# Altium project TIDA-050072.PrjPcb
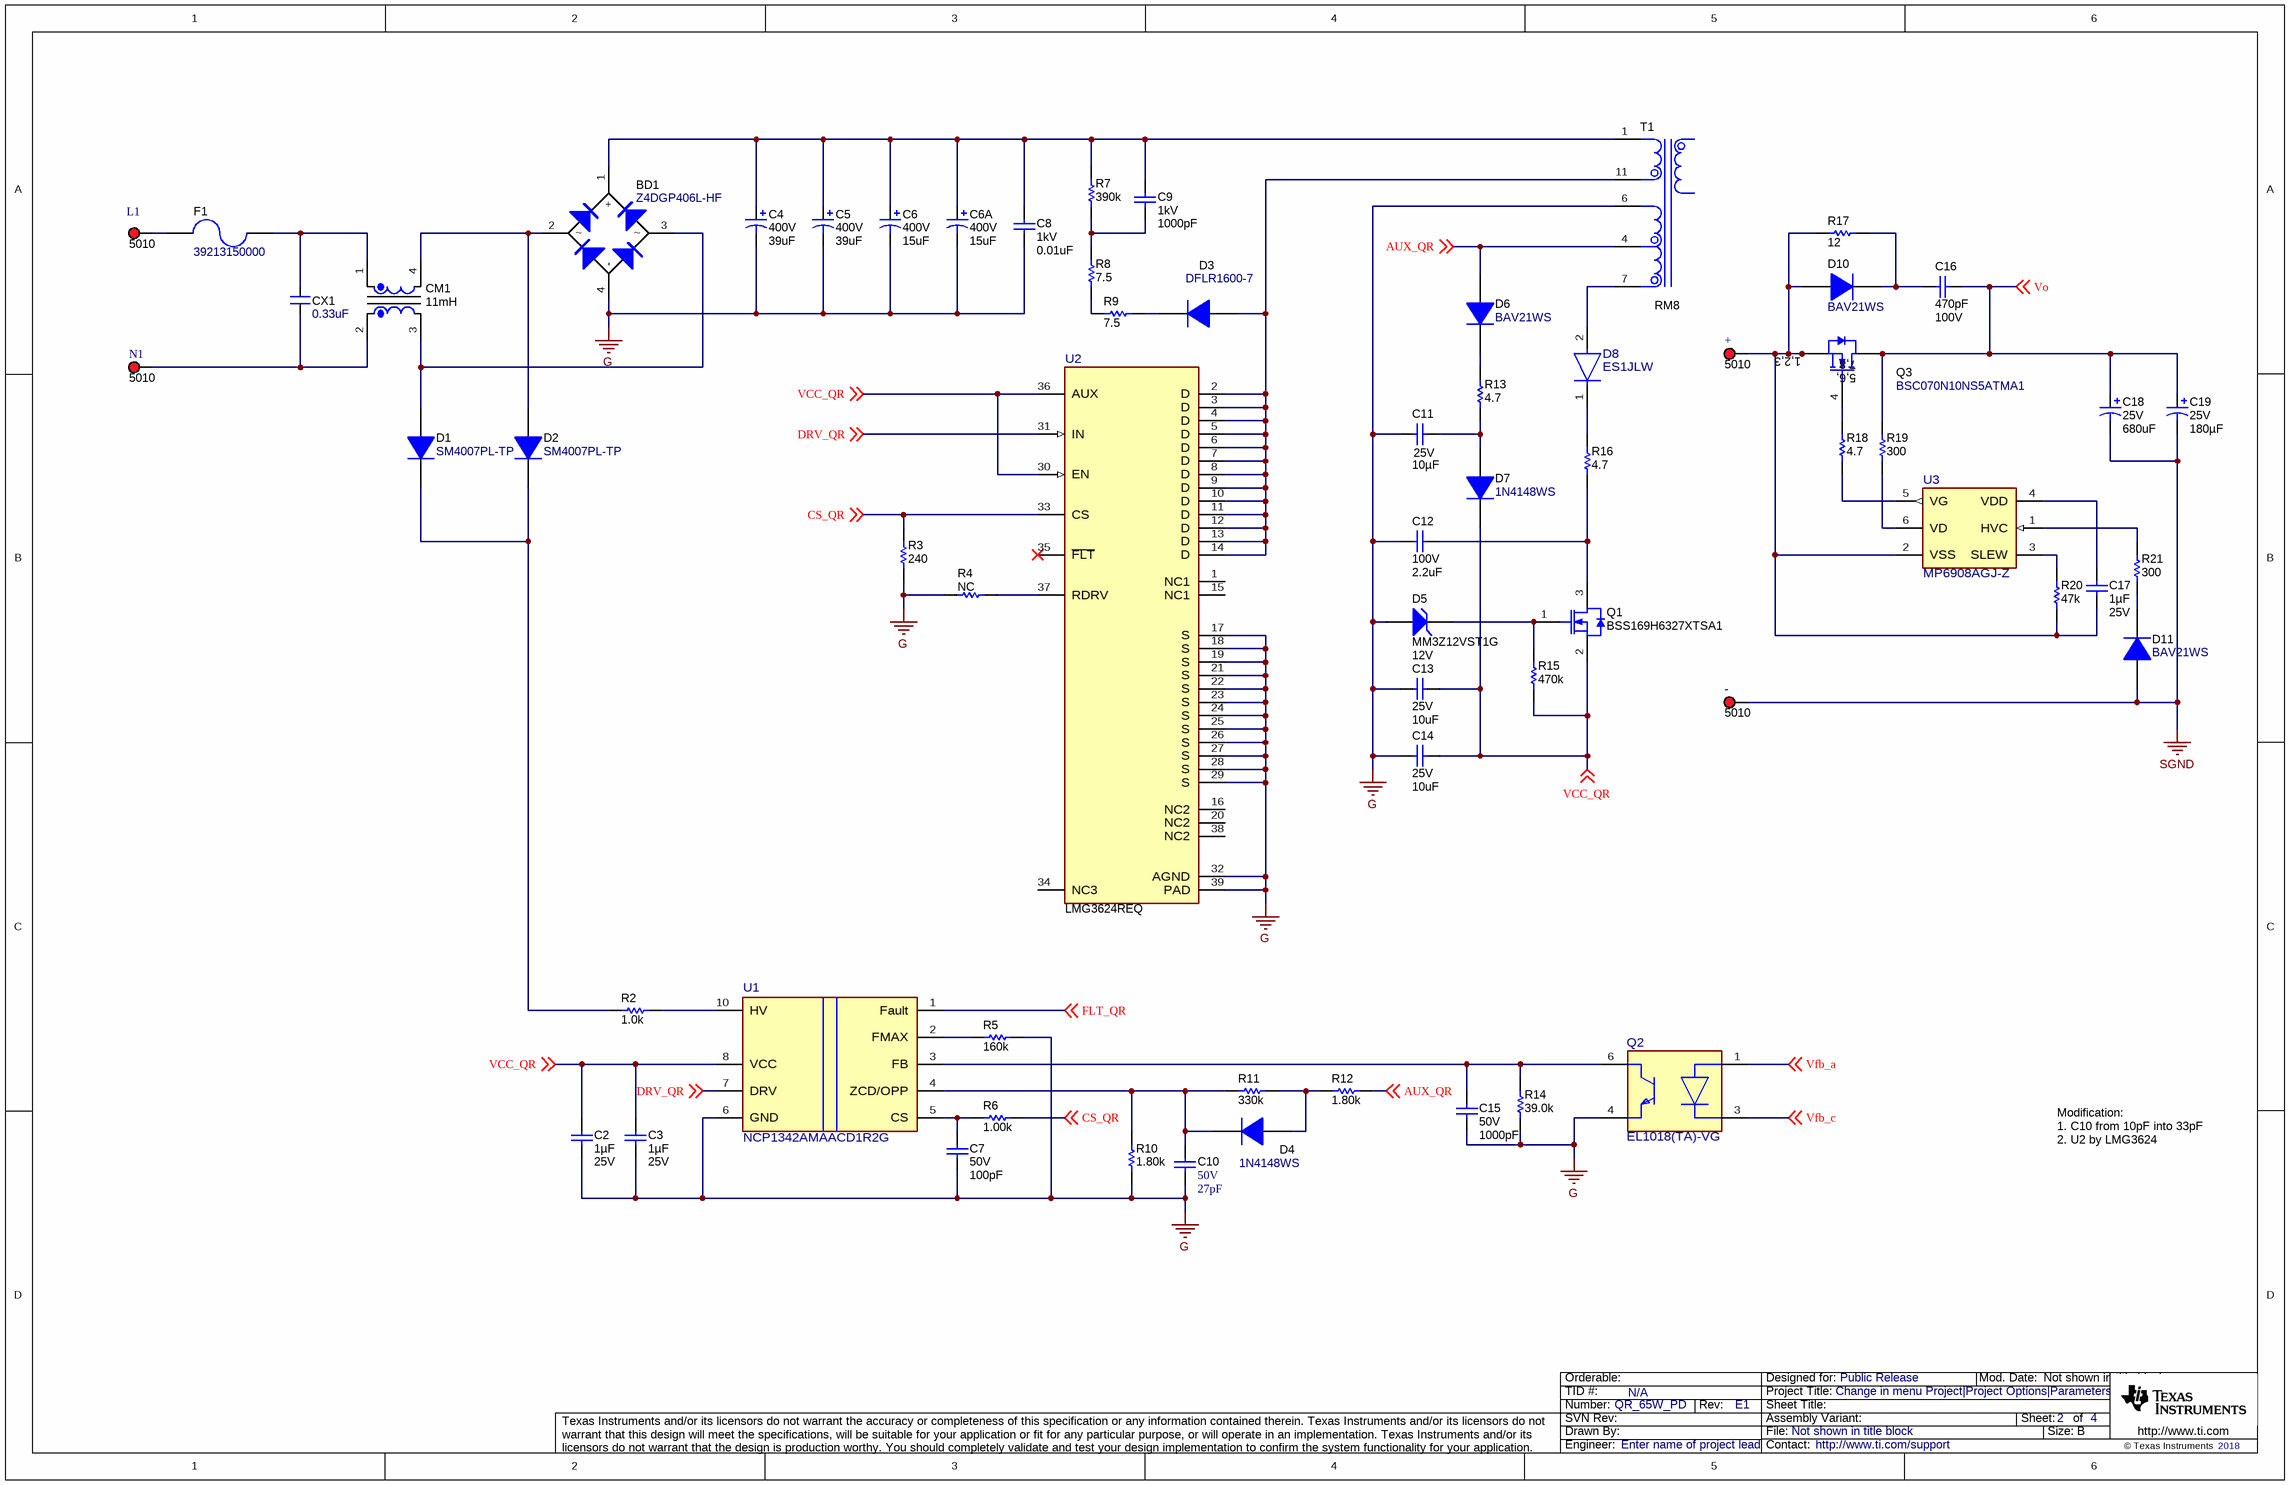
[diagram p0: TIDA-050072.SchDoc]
CopyrightYear: 2018; PCB_Layout: Who did the Layout?; PCB_Rev: E1; PRJ_Customer: Public Release; PRJ_Engineer: Enter name of project lead; PRJ_Number: QR_65W_PD; PRJ_Title: Change in menu Project|Project Options|Parameters; SCH_Rev: E1; TechSupport: http://www.ti.com/support; TID: N/A
5 sheets, 105 parts. Net scope: global (net labels, ports and power ports of the same name join across sheets).
Board file: TIDA-050072.PcbDoc
Sheets:
  TIDA-050072.SchDoc
  TIDA-050072_BlankSheet.SchDoc
  TIDA-050072_CoverSheet.SchDoc
  TIDA-050072_Hardware.SchDoc
  TIDA-050072_PD_Board.SchDoc

## Sheet TIDA-050072.SchDoc
size 431 x 279 mm; Date: Not shown in title block; ApprovedBy: Not shown in title block; CheckedBy: Not shown in title block; Author: Not shown in title block; CompanyName: Not shown in title block; Engineer: Not shown in title block; Organization: Not shown in title block; Address1: Not shown in title block; Address2: Not shown in title block; Address3: Not shown in title block; Address4: Not shown in title block; DocumentNumber: 2; Revision: Use project parameter SCH_Rev; SheetNumber: 2; SheetTotal: 4; PageSetup: Record=PageOptions¦CenterHorizontal=True¦CenterVertical=True¦PrintScale=1.00¦XCorrection=1.00¦YCorrection=1.00¦PrintKind=0¦BorderSize=5000000¦LeftOffset=0¦BottomOffset=0¦Orientation=2¦PaperLength=1000¦PaperWidth=1000¦Scale=100¦PaperSource=15¦PrintQuality=600¦MediaType=1¦DitherType=10¦PaperKind=Letter¦PrintScaleMode=1

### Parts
+  5010  [Keystone5010]
-  5010  [Keystone5010]
BD1  Z4DGP406L-HF  [Z4-D]
C2  Cap_F: 1µF  VDC_V: 25V  [0603_HV]  (hidden comment: GCM188R71E105KA64D)
C3  Cap_F: 1µF  VDC_V: 25V  [0603_HV]  (hidden comment: GCM188R71E105KA64D)
C4  VDC_V: 400V  ValueDisplayed: 39uF  [CY_1250x2000]  (hidden comment: 400LXW39MEFR12.5X20)
C5  VDC_V: 400V  ValueDisplayed: 39uF  [CY_1250x2000]  (hidden comment: 400LXW39MEFR12.5X20)
C6  VDC_V: 400V  ValueDisplayed: 15uF  [AX_800x900]  (hidden comment: 400AX4.7MTA8X9)
C6A  VDC_V: 400V  ValueDisplayed: 15uF  [AX_800x900]  (hidden comment: 400AX4.7MTA8X9)
C7  VDC_V: 50V  ValueDisplayed: 100pF  [0603_HV]  (hidden comment: C0603C101J5GAC)
C8  VDC_V: 1kV  ValueDisplayed: 0.01uF  [1206]  (hidden comment: VJ1206Y103KXGAT5Z)
C9  VDC_V: 1kV  ValueDisplayed: 1000pF  [1206]  (hidden comment: GRM31BR73A102KW01L)
C10  VDC_V: 50V  ValueDisplayed: 27pF  [0603]  (hidden comment: GRM1885C1H270JA01D)
C11  VDC_V: 25V  ValueDisplayed: 10µF  [0805]  (hidden comment: CC0805KKX5R8BB106)
C12  VDC_V: 100V  ValueDisplayed: 2.2uF  [1206_190]  (hidden comment: GRM31CR72A225KA73L)
C13  VDC_V: 25V  ValueDisplayed: 10uF  [1206_190]  (hidden comment: C3216X7R1E106K160AE)
C14  VDC_V: 25V  ValueDisplayed: 10uF  [1206_190]  (hidden comment: C3216X7R1E106K160AE)
C15  VDC_V: 50V  ValueDisplayed: 1000pF  [0603_HV]  (hidden comment: C0603C102J5GACTU)
C16  Cap_F: 470pF  VDC_V: 100V  [0603_HV]  (hidden comment: 06031C471KAT2A)
C17  Cap_F: 1µF  VDC_V: 25V  [0603_HV]  (hidden comment: GCM188R71E105KA64D)
C18  VDC_V: 25V  ValueDisplayed: 680uF  [Chemi-Con_800x1500]  (hidden comment: A750KW687M1EAAE016)
C19  VDC_V: 25V  ValueDisplayed: 180µF  [Panasonic_D8]  (hidden comment: EEH-ZKE181XUP)
CM1  11mH  [CM_20x11_planwire]
CX1  value 0.33uF  [Xcap_15x8.5]  (hidden comment: 890324024003)
D1  SM4007PL-TP  [SOD-123FL]
D2  SM4007PL-TP  [SOD-123FL]
D3  DFLR1600-7  [PowerDI123]
D4  1N4148WS  [SOD-323]
D5  MM3Z12VST1G  value 12V  [SOD-323]
D6  BAV21WS  [SOD-323]
D7  1N4148WS  [SOD-323]
D8  ES1JLW  [FP-UF1JLWHRVG_SOD-123-MFG]
D10  BAV21WS  [SOD-323]
D11  BAV21WS  [SOD-323]
F1  39213150000  [FUSE_392]
L1  5010  [Keystone5010]
N1  5010  [Keystone5010]
Q1  BSS169H6327XTSA1  [SOT-23]
Q2  EL1018(TA)-VG  [FP-TLP383(GR-TPL,E_SO6-4-MFG]
Q3  BSC070N10NS5ATMA1  [PG-TDSON-8]
R2  ValueDisplayed: 1.0k  [1206]  (hidden comment: CRCW12061K00JNEA)
R3  ValueDisplayed: 240  [0603_HV]  (hidden comment: RC0603FR-07240RL)
R4  ValueDisplayed: NC  [0603_HV]  (hidden comment: RC0603JR-0747KL)
R5  ValueDisplayed: 160k  [0603_HV]  (hidden comment: CRCW0603160KFKEA)
R6  ValueDisplayed: 1.00k  [0603_HV]  (hidden comment: ERJ-3EKF1001V)
R7  ValueDisplayed: 390k  [1206]  (hidden comment: CRCW1206390KJNEA)
R8  ValueDisplayed: 7.5  [1206]  (hidden comment: CRCW12067R50JNEA)
R9  ValueDisplayed: 7.5  [1206]  (hidden comment: CRCW12067R50JNEA)
R10  ValueDisplayed: 1.80k  [0603_HV]  (hidden comment: RC0603FR-071K8L)
R11  ValueDisplayed: 330k  [0603_HV]  (hidden comment: RC0603FR-07330KL)
R12  ValueDisplayed: 1.80k  [0603_HV]  (hidden comment: RC0603FR-071K8L)
R13  ValueDisplayed: 4.7  [0603_HV]  (hidden comment: CRCW06034R70JNEA)
R14  ValueDisplayed: 39.0k  [0603_HV]  (hidden comment: RC0603FR-0739KL)
R15  ValueDisplayed: 470k  [0603_HV]  (hidden comment: CRCW0603470KJNEA)
R16  ValueDisplayed: 4.7  [0603_HV]  (hidden comment: CRCW06034R70JNEA)
R17  ValueDisplayed: 12  [0805L]  (hidden comment: ERJ-6GEYJ120V)
R18  ValueDisplayed: 4.7  [0603_HV]  (hidden comment: CRCW06034R70JNEA)
R19  ValueDisplayed: 300  [0603_HV]  (hidden comment: RC0603JR-07300RL)
R20  ValueDisplayed: 47k  [0603_HV]  (hidden comment: RC0603JR-0747KL)
R21  ValueDisplayed: 300  [0603_HV]  (hidden comment: RC0603JR-07300RL)
T1  RM8  [RM8]
U1  NCP1342AMAACD1R2G  [FP-NCP1342AMAACD1R2G_SOIC9-MFG]
U2  PartNumber: LMG3624REQ  [REQ0038A-MFG]  (hidden comment: LMG3622REQ)
U3  MP6908AGJ-Z  [FP-MP6908GJ-Z_TSOT23-6-MFG]

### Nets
G: BD1.4(-) C2.2 C3.2 C4.2(-) C5.2(-) C6.2(-) C6A.2(-) C7.2 C8.2 C10.2 C11.2 C12.2 C13.2 C14.2 C15.2 D5.2(A) Q2.4(Emitter) R3.2 R4.2 R5.2 R10.1 R14.1 T1.6 U1.6(GND) U2.17(S) U2.18(S) U2.19(S) U2.21(S) U2.22(S) U2.23(S) U2.24(S) U2.25(S) U2.26(S) U2.27(S) U2.28(S) U2.29(S) U2.32(AGND) U2.39(PAD)
SGND: -.1 C18.2(-) C19.2(-) D11.2(A)
AUX_QR: D6.2(A) R12.2 T1.4 ; off-sheet AUX_QR
CS_QR: R3.1 R6.1 U2.33(CS) ; off-sheet CS_QR
DRV_QR: U1.7(DRV) U2.31(IN) ; off-sheet DRV_QR
FLT_QR: U1.1(Fault) ; off-sheet FLT_QR
VCC_QR: C2.1 C3.1 C13.1 C14.1 D7.1(K) Q1.2(S) R15.1 U1.8(VCC) U2.30(EN) U2.36(AUX) ; off-sheet VCC_QR
Vfb_a: Q2.1(Anode) ; off-sheet Vfb_a
Vfb_c: Q2.3(Cathode) ; off-sheet Vfb_c
Vo: C16.1 C18.1(+) C19.1(+) Q3.5(D) Q3.6(D) Q3.7(D) Q3.8(D) Q3.9(D) R19.2 ; off-sheet Vo
Net+_1: +.1 C17.2 D10.2(A) Q3.1(S) Q3.2(S) Q3.3(S) R17.1 R20.1 U3.2(VSS)
NetBD1_1: BD1.1(+) C4.1(+) C5.1(+) C6.1(+) C6A.1(+) C8.1 C9.1 R7.2 T1.1
NetBD1_2: BD1.2 CM1.4 D2.2(A)
NetBD1_3: BD1.3 CM1.3 D1.2(A)
NetC7_1: C7.1 R6.2 U1.5(CS)
NetC9_2: C9.2 R7.1 R8.2
NetC10_1: C10.1 D4.1(K) R10.2 R11.1 U1.4(ZCD/OPP)
NetC11_1: C11.1 D7.2(A) R13.1
NetC12_1: C12.1 Q1.3(D) R16.1
NetC15_1: C15.1 Q2.6(Collector) R14.2 U1.3(FB)
NetC16_2: C16.2 D10.1(K) R17.2
NetC17_1: C17.1 U3.4(VDD)
NetCM1_1: CM1.1 CX1.1 F1.1
NetCM1_2: CM1.2 CX1.1 N1.1
NetD1_1: D1.1(K) D2.1(K) R2.1
NetD3_1: D3.1(K) R9.2
NetD3_2: D3.2(A) T1.11 U2.2(D) U2.3(D) U2.4(D) U2.5(D) U2.6(D) U2.7(D) U2.8(D) U2.9(D) U2.10(D) U2.11(D) U2.12(D) U2.13(D) U2.14(D)
NetD4_2: D4.2(A) R11.2 R12.1
NetD5_1: D5.1(K) Q1.1(G) R15.2
NetD6_1: D6.1(K) R13.2
NetD8_1: D8.1(CATHODE) R16.2
NetD8_2: D8.2(ANODE) T1.7
NetD11_1: D11.1(K) R21.2
NetF1_2: F1.2 L1.1
NetQ3_4: Q3.4(G) R18.2
NetR2_2: R2.2 U1.10(HV)
NetR4_1: R4.1 U2.37(RDRV)
NetR5_1: R5.1 U1.2(FMAX)
NetR8_1: R8.1 R9.1
NetR18_1: R18.1 U3.5(VG)
NetR19_1: R19.1 U3.6(VD)
NetR20_2: R20.2 U3.3(SLEW)
NetR21_1: R21.1 U3.1(HVC)

Not connected (* = marked no-connect by the designer): U2 1(NC1) 15(NC1) 16(NC2) 20(NC2) 34(NC3) 35(~{FLT})* 38(NC2)

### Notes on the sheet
- Modification:
  1. C10 from 10pF into 33pF
  2. U2 by LMG3624

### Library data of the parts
+ - L1 N1 = CMP-0055147-2: Test Point, Multipurpose, Red, TH; Manufacturer: Keystone Electronics; CT: TRUE; ContactFinish: Silver; Green_Lifecycle: Active; CNHeader: FALSE; Green_REACh: Passed
BD1 = CMP-0029244-3: Diode, P-N-Bridge, 600 V, 4 A, Z4-D; Manufacturer: Comchip Technology; Value1: 4A; SizeZ_mm: 1.55; Value: 600V; SizeArea_mm2: 85.05; SizeY_mm: 8.1; SizeAreaWB_mm2: 126.25; Value2: 0.95V; Green_REACh: Incomplete; TJmax_C: 175°C; Green_Lifecycle: Not Set; Vf_V: 950mV; AEC Qualified: N; AEC Category: Q101; SizeX_mm: 10.5
C2 C3 C17 = CMP-0007139-2: CAP, CERM, 1 uF, 25 V, +/- 10%, X7R, AEC-Q200 Grade 1, 0603; Manufacturer: MuRata; TaMin_C: -55°C; Polarized: N; SizeAreaWB_mm2: 4.68; Value1: Unknown; U/M: EA; Value: 1uF; TaMax_C: 125°C; SizeZ_mm: 1; SizeX_mm: 1.6; SizeY_mm: 0.8; Cap_Case: 0603; SizeArea_mm2: 1.28; AEC Qualified: Y; AEC Category: Q200
C4 C5 = CMP-0010248-2: CAP, AL, 39 uF, 400 V, +/- 20%, TH; Manufacturer: Rubycon; TaMin_C: -40°C; Polarized: Y; SizeAreaWB_mm2: 210.25; Value1: Unknown; U/M: EA; Value: 39uF; TaMax_C: 105°C; SizeZ_mm: 21.5; SizeX_mm: 12.5; SizeArea_mm2: 156.25; CompType: Capacitor; AEC Qualified: N; Cap_F: 39µF; IRMS_A: 360mA; AEC Category: Q200
C6 C6A = CMP-0009969-1: CAP ALUM 15UF 20% 400V RADIAL; Manufacturer: Rubycon; PartNumber: 400AX15MEFC8X20; TaMin_C: -40°C; Polarized: Y; SizeAreaWB_mm2: 100; Value1: Unknown; U/M: EA; TaMax_C: 105°C; SizeZ_mm: 10.5; SizeX_mm: 8; Cap_Case: 8x20mm; SizeArea_mm2: 64; CompType: Capacitor; AEC Qualified: N; Cap_F: 15µF; IRMS_A: 50mA; AEC Category: Q200
C7 = CMP-0006840-3: CAP, CERM, 100 pF, 50 V, +/- 5%, C0G/NP0, 0603; Manufacturer: Kemet; TaMin_C: -55°C; Polarized: N; SizeAreaWB_mm2: 4.68; Value1: Unknown; U/M: EA; Value: 100pF; TaMax_C: 125°C; SizeZ_mm: 1; SizeX_mm: 1.6; SizeY_mm: 0.8; Cap_Case: 0603; SizeArea_mm2: 1.28; AEC Category: Q200
C8 = CMP-0009043-2: CAP, CERM, 0.01 uF, 1000 V, +/- 10%, X7R, 1206; Manufacturer: Vishay-Vitramon; TaMin_C: -55°C; Polarized: N; SizeAreaWB_mm2: 10.92; Value1: Unknown; U/M: EA; Value: 0.01uF; TaMax_C: 125°C; SizeZ_mm: 1.35; SizeX_mm: 3.2; SizeY_mm: 1.6; Value2: 1000V; SizeArea_mm2: 5.12; Cap_F: 10nF; AEC Category: Q200
C9 = CMP-0008916-2: CAP, CERM, 1000 pF, 1000 V, +/- 10%, X7R, 1206; Manufacturer: MuRata; TaMin_C: -55°C; Polarized: N; SizeAreaWB_mm2: 10.92; Value1: Unknown; U/M: EA; Value: 1000pF; TaMax_C: 125°C; SizeZ_mm: 1.35; SizeX_mm: 3.2; SizeY_mm: 1.6; Value2: 1000V; SizeArea_mm2: 5.12; Cap_F: 1nF; AEC Category: Q200
C10 = CMP-0007202-4: CAP, CERM, 27 pF, 50 V, +/- 5%, C0G/NP0, 0603; Manufacturer: MuRata; TaMin_C: -55°C; Polarized: N; SizeAreaWB_mm2: 4.68; Value1: Unknown; U/M: EA; Value: 27pF; TaMax_C: 125°C; SizeZ_mm: 1; SizeX_mm: 1.6; SizeY_mm: 0.8; SizeArea_mm2: 1.28; AEC Category: Q200
C11 = CMP-0084177-1: CAP, CERM, 10 µF, 25 V,+/- 10%, X5R, 0805; Manufacturer: Yageo; SizeAreaWB_mm2: 6.75; SizeArea_mm2: 2.5; AEC Qualified: N; AEC Category: Q200; Value: 10uF; TaMax_C: 85°C; SizeZ_mm: 1.45; TaMin_C: -55°C; SizeY_mm: 1.25; U/M: EA; SizeX_mm: 2
C12 = CMP-0008971-1: CAP, CERM, 2.2 uF, 100 V, +/- 10%, X7R, 1206_190; Manufacturer: MuRata; TaMin_C: -55°C; Polarized: N; SizeAreaWB_mm2: 10.92; Value1: Unknown; U/M: EA; Value: 2.2uF; TaMax_C: 125°C; SizeZ_mm: 1.9; SizeX_mm: 3.2; SizeY_mm: 1.6; Cap_Case: 1206; SizeArea_mm2: 5.12; Cap_F: 2.2µF; AEC Category: Q200
C13 C14 = CMP-00003-1: CAP, CERM, 10 uF, 25 V, +/- 10%, X7R, 1206_190; Manufacturer: TDK; SizeArea_mm2: 5.12; SizeAreaWB_mm2: 10.92; TaMin_C: -55°C; Polarized: N; Value: 10uF; SizeY_mm: 1.6; AEC Category: Q200; U/M: EA; Cap_F: 10µF; SizeZ_mm: 1.9; SizeX_mm: 3.2; TaMax_C: 125°C; Value1: Unknown; Cap_Case: 1206
C15 = CMP-0006843-4: CAP, CERM, 1000 pF, 50 V, +/- 5%, C0G/NP0, 0603; Manufacturer: Kemet; TaMin_C: -55°C; Polarized: N; SizeAreaWB_mm2: 4.68; Value1: Unknown; U/M: EA; Value: 1000pF; TaMax_C: 125°C; SizeZ_mm: 1; SizeX_mm: 1.6; SizeY_mm: 0.8; Cap_Case: 0603; SizeArea_mm2: 1.28; Cap_F: 1nF; AEC Category: Q200
C16 = CMP-0006744-2: CAP, CERM, 470 pF, 100 V, +/- 10%, X7R, 0603; Manufacturer: AVX; TaMin_C: -55°C; ESR_ohm: 0.397; Polarized: N; SizeAreaWB_mm2: 4.68; Value1: 0.397 ohm; U/M: EA; Value: 470pF; TaMax_C: 125°C; SizeZ_mm: 1; SizeX_mm: 1.6; SizeY_mm: 0.8; Cap_Case: 0603; SizeArea_mm2: 1.28; AEC Category: Q200
C18 = CMP-0010407-1: CAP ALUM POLY 680UF 20% 25V T/H; Manufacturer: KEMET; TaMin_C: -40°C; Polarized: Y; SizeAreaWB_mm2: 100; Value1: Unknown; U/M: EA; TaMax_C: 105°C; SizeZ_mm: 16.5; SizeX_mm: 8; Cap_Case: 8x15; SizeArea_mm2: 64; CompType: Capacitor; AEC Qualified: N; Cap_F: 680µF; IRMS_A: 995mA; AEC Category: Q200
C19 = CMP-0860234-1: CAP ALUM POLY HYB 180UF 25V SMD; Manufacturer: Panasonic; Tolerance_%: 20%; Cap_Case: 6.3x8mm; TaMax_C: 105°C; Value1: 0.03 ohm; AEC Qualified: Y; SizeY_mm: 6.6; TaMin_C: -55°C; SizeAreaWB_mm2: 73.96; CompType: Capacitor; SizeArea_mm2: 43.56; IRMS_A: 2A; AEC Grade: 2; AEC Category: Q200; SizeZ_mm: 8; ESR_ohm: 0.03
CM1 = CM_Choke_Planar: Manufacturer: Used in BOM report; CompType: Used in some BOM reports.  Useful for finding later.
CX1 = CX: CAP FILM 0.33UF 10% 275VAC RAD; Manufacturer: Würth Elektronik
D1 D2 = CMP-0077021-2: Diode, Standard Recovery Rectifier, 1000 V, 1 A, SOD-123FL; Manufacturer: Micro Commercial Components; SizeAreaWB_mm2: 12.19; Value: 1000V; Vr_V: 1kV; Io_A: 1A; SizeX_mm: 3.6; SizeArea_mm2: 5.94; SizeZ_mm: 0.98; Green_Lifecycle: Not Set; Green_REACh: Incomplete; TJmax_C: 175°C; AEC Category: Q101; Vf_V: 1.1V; SizeY_mm: 1.65
D3 = CMP-0076978-2: Diode, Standard Recovery Rectifier, 600 V, 1 A, PowerDI123; Manufacturer: Diodes Inc.; AEC Category: Q101; SizeAreaWB_mm2: 13.066; SizeY_mm: 1.78; Value2: 1.1V; TJmax_C: 150°C; Green_Lifecycle: Not Set; Value1: 1A; Value: 600V; SizeZ_mm: 0.98; SizeX_mm: 3.7; SizeArea_mm2: 6.586; Green_REACh: Incomplete
D4 D7 = CMP-0079597-2: Diode, Switching, 75 V, 0.15 A, AEC-Q101, SOD-323; Manufacturer: Diodes Inc.; SizeX_mm: 2.7; Vf_V: 1.25V; AEC Qualified: Y; SizeArea_mm2: 3.645; AEC Category: Q101; SizeAreaWB_mm2: 8.695; Io_A: 150mA; SizeZ_mm: 1; Value1: 0.15A; SizeY_mm: 1.35; TJmax_C: 150°C; Vr_V: 75V; Value: 75V
D5 = CMP-0085757-1: Diode, Zener, 12 V, 300 mW, SOD-323; Manufacturer: ON Semiconductor; SizeAreaWB_mm2: 8.695; AEC Qualified: N; SizeZ_mm: 1; Power_W: 300mW; AEC Category: Q101; SizeArea_mm2: 3.645; Value1: 0.3W; SizeX_mm: 2.7; RJA_CperW: 416; SizeY_mm: 1.35
D6 D10 D11 = CMP-0029165-1: Diode, Switching, 250 V, 0.25 A, AEC-Q101, SOD-323; Manufacturer: Diodes Inc.; Io_A: 250mA; Green_Lifecycle: Active; SizeAreaWB_mm2: 8.695; Vr_V: 250V; Green_REACh: Passed; Value1: 0.25A; TJmax_C: 150°C; U/M: EA; Value: 250V; SizeZ_mm: 1; SizeX_mm: 2.7; SizeY_mm: 1.35; Vf_V: 1.25V; SizeArea_mm2: 3.645; AEC Qualified: Y; AEC Category: Q101
D8 = CMP-0090530-1: Diode Standard 600V 1A Surface Mount SOD-123W; Manufacturer: Taiwan Semiconductor; AEC Qualified: Yes; Max Surge Forward Current: 30A; Peak Reverse Current: 1uA; AEC Grade: Grade 0; TJmax_C: 150°C; ValueDisplayed: 15pF; SizeZ_mm: 1.02mm
F1 = CMP-0003561-1: Fuse, 3.15 A, 250VAC/VDC, TH; Manufacturer: Littelfuse; Irating_A: 3.15A; VAC_V: 250V
Q1 = CMP-0000949-3: MOSFET, N-CH, Depletion Mode, 100 V, 0.17 A, AEC-Q101, SOT-23; Alternate Manufacturer: None; Manufacturer: Infineon Technologies; SizeZ_mm: 1.1; ChType: N; Value2: 2.1 nC; VdsMax_V: 100V; SizeX_mm: 2.5; SizeY_mm: 3; Vgs_V: 20V; QgTyp_nC: 2.1; AEC Qualified: Y; Value: 100V; SizeArea_mm2: 7.5; AEC Category: Q101; IdsMax_A: 170mA; SizeAreaWB_mm2: 14
Q2 = CMP-0087394-2: Optoisolator Transistor Output 5000Vrms 1 Channel 6-SO; Manufacturer: Toshiba; CTR (Max): 300%; CTR (Min): 100%; SizeZ_mm: 2.3mm
Q3 = CMP-0000935-1: MOSFET, N-CH, 100 V, 80 A, PG-TDSON-8; Alternate Manufacturer: None; Manufacturer: Infineon Technologies; SizeZ_mm: 1.12; ChType: N; Value2: 30 nC; VdsMax_V: 100V; SizeX_mm: 5.99; SizeY_mm: 4.9; Vgs_V: 20V; QgTyp_nC: 30; Value: 100V; SizeArea_mm2: 29.351; AEC Category: Q101; IdsMax_A: 80A; SizeAreaWB_mm2: 55.131; U/M: EA
R2 = CMP-0018603-1: RES, 1.0 k, 5%, 0.25 W, 1206; Manufacturer: Vishay-Dale; Power_W: 250mW; TempCo: 200 ppm/C; Value_Code: 1k00; U/M: EA; Value: 1.0k; EIA_Code: E24; Res_ohm: 1k; SizeX_mm: 3.2; SizeY_mm: 1.6; SizeZ_mm: 1.35; Value2: 0.25W; SizeArea_mm2: 5.12; VDC_V: 200V; AEC Category: Q200
R3 = CMP-0022938-5: RES, 240, 1%, 0.1 W, 0603; Manufacturer: Yageo; Power_W: 100mW; TempCo: 100 ppm/C; Value_Code: 240R; Value: 240; SizeX_mm: 1.6; SizeY_mm: 0.8; SizeZ_mm: 1; Value2: 0.1W; SizeArea_mm2: 1.28; AEC Qualified: N; VDC_V: 75V; AEC Category: Q200; SizeAreaWB_mm2: 4.68
R4 R20 = CMP-0025925-5: RES, 47 k, 5%, 0.1 W, 0603; Manufacturer: Yageo; Power_W: 100mW; TempCo: 100 ppm/C; Value_Code: 47k0; Value: 47k; EIA_Code: E24; SizeX_mm: 1.6; SizeY_mm: 0.8; SizeZ_mm: 1; Value2: 0.1W; SizeArea_mm2: 1.28; AEC Qualified: N; VDC_V: 75V; AEC Category: Q200; SizeAreaWB_mm2: 4.68
R5 = CMP-0022072-1: RES, 160 k, 1%, 0.1 W, 0603; Manufacturer: Vishay-Dale; Power_W: 100mW; TempCo: 100 ppm/C; U/M: EA; Value: 160k; SizeX_mm: 1.6; SizeY_mm: 0.8; SizeZ_mm: 1; Value2: 0.1W; SizeArea_mm2: 1.28; VDC_V: 75V; AEC Category: Q200
R6 = CMP-0022680-2: RES, 1.00 k, 1%, 0.1 W, 0603; Manufacturer: Panasonic; Power_W: 100mW; TempCo: 100 ppm/C; Value_Code: 1k00; U/M: EA; Value: 1.00k; EIA_Code: E96; Res_ohm: 1k; SizeX_mm: 1.6; SizeY_mm: 0.8; SizeZ_mm: 1; SizeArea_mm2: 1.28; VDC_V: 75V; AEC Category: Q200; Value2: 0.1W
R7 = CMP-0018664-2: RES, 390 k, 5%, 0.25 W, 1206; Manufacturer: Vishay-Dale; Power_W: 250mW; TempCo: 200 ppm/C; U/M: EA; Value: 390k; EIA_Code: E24; SizeX_mm: 3.2; SizeY_mm: 1.6; SizeZ_mm: 1.35; Value2: 0.25W; SizeArea_mm2: 5.12; VDC_V: 200V; AEC Category: Q200
R8 R9 = CMP-0018730-2: RES, 7.5, 5%, 0.25 W, 1206; Manufacturer: Vishay-Dale; Power_W: 250mW; TempCo: 200 ppm/C; Value_Code: 7R50; U/M: EA; Value: 7.5; EIA_Code: E24; SizeX_mm: 3.2; SizeY_mm: 1.6; SizeZ_mm: 1.35; Value2: 0.25W; SizeArea_mm2: 5.12; VDC_V: 200V; AEC Category: Q200
R10 R12 = CMP-0022892-5: RES, 1.80 k, 1%, 0.1 W, 0603; Manufacturer: Yageo; Power_W: 100mW; TempCo: 100 ppm/C; Value_Code: 1k80; Value: 1.80k; Res_ohm: 1.8k; SizeX_mm: 1.6; SizeY_mm: 0.8; SizeZ_mm: 1; Value2: 0.1W; SizeArea_mm2: 1.28; AEC Qualified: N; VDC_V: 75V; AEC Category: Q200; SizeAreaWB_mm2: 4.68
R11 = CMP-0023032-4: RES, 330 k, 1%, 0.1 W, 0603; Manufacturer: Yageo; Power_W: 100mW; TempCo: 100 ppm/C; Value: 330k; SizeX_mm: 1.6; SizeY_mm: 0.8; SizeZ_mm: 1; Value2: 0.1W; SizeArea_mm2: 1.28; AEC Qualified: N; VDC_V: 75V; AEC Category: Q200; SizeAreaWB_mm2: 4.68
R13 R16 R18 = CMP-0025821-1: RES, 4.7, 5%, 0.1 W, 0603; Manufacturer: Vishay-Dale; Power_W: 100mW; TempCo: 200 ppm/C; Value_Code: 4R70; U/M: EA; Value: 4.7; EIA_Code: E24; SizeX_mm: 1.6; SizeY_mm: 0.8; SizeZ_mm: 1; Value2: 0.1W; SizeArea_mm2: 1.28; VDC_V: 75V; AEC Category: Q200
R14 = CMP-0023073-5: RES, 39.0 k, 1%, 0.1 W, 0603; Manufacturer: Yageo; Power_W: 100mW; TempCo: 100 ppm/C; Value_Code: 39k0; Value: 39.0k; Res_ohm: 39k; SizeX_mm: 1.6; SizeY_mm: 0.8; SizeZ_mm: 1; Value2: 0.1W; SizeArea_mm2: 1.28; AEC Qualified: N; VDC_V: 75V; AEC Category: Q200; SizeAreaWB_mm2: 4.68
R15 = CMP-0025812-1: RES, 470 k, 5%, 0.1 W, 0603; Manufacturer: Vishay-Dale; Power_W: 100mW; TempCo: 200 ppm/C; U/M: EA; Value: 470k; EIA_Code: E24; SizeX_mm: 1.6; SizeY_mm: 0.8; SizeZ_mm: 1; Value2: 0.1W; SizeArea_mm2: 1.28; VDC_V: 75V; AEC Category: Q200
R17 = CMP-0020631-1: RES, 12, 5%, 0.125 W, 0805; Manufacturer: Panasonic; Power_W: 125mW; TempCo: 200 ppm/C; Value_Code: 12R0; U/M: EA; Value: 12; EIA_Code: E24; SizeX_mm: 2; SizeY_mm: 1.25; SizeZ_mm: 1.45; Value2: 0.125W; SizeArea_mm2: 2.5; VDC_V: 150V; AEC Category: Q200
R19 R21 = CMP-0025910-5: RES, 300, 5%, 0.1 W, 0603; Manufacturer: Yageo; Power_W: 100mW; TempCo: 100 ppm/C; Value_Code: 300R; Value: 300; EIA_Code: E24; SizeX_mm: 1.6; SizeY_mm: 0.8; SizeZ_mm: 1; Value2: 0.1W; SizeArea_mm2: 1.28; AEC Qualified: N; VDC_V: 75V; AEC Category: Q200; SizeAreaWB_mm2: 4.68
T1 = RM8_65W: Manufacturer: Used in BOM report; CompType: Used in some BOM reports.  Useful for finding later.
U1 = CMP-0094882-1: Converter Offline Flyback Topology 50kHz; Manufacturer: onsemi; SizeZ_mm: 2mm; Switching Frequency: 25kHz; Number Of Outputs: 1; AEC Qualified: No; Output Type: Other; Min Supply Voltage: 8.5V; Nominal Supply Current: 0.115-1mA; Max Supply Voltage: 28V; Max Power Dissipation: 330mW; TJmax_C: +125°C; Standoff Height: 0.1mm
U2 = CMP-0096535-2: 650-V GaN FET With Integrated Driver and Current Sense Emulation; Manufacturer: Texas Instruments; Number Of Drivers: 1; CompType: IC; Max Supply Voltage: 26V; SizeZ_mm: 1mm; AEC Category: Q200; Min Supply Voltage: 10V; AEC Qualified: No; TJmax_C: +175°C; Standoff Height: 0mm
U3 = CMP-0086802-1: FAST TURN-OFF INTELLIGENT RECTIF; Manufacturer: Monolithic Power Systems; SizeZ_mm: 1mm

## Sheet TIDA-050072_BlankSheet.SchDoc
size 431 x 279 mm; Date: Not shown in title block; ApprovedBy: Not shown in title block; CheckedBy: Not shown in title block; Author: Not shown in title block; CompanyName: Not shown in title block; Engineer: Not shown in title block; Organization: Not shown in title block; Address1: Not shown in title block; Address2: Not shown in title block; Address3: Not shown in title block; Address4: Not shown in title block; DocumentNumber: 2; Revision: Use project parameter SCH_Rev; SheetNumber: 2; SheetTotal: 3; PageSetup: Record=PageOptions¦CenterHorizontal=True¦CenterVertical=True¦PrintScale=1.00¦XCorrection=1.00¦YCorrection=1.00¦PrintKind=0¦BorderSize=5000000¦LeftOffset=0¦BottomOffset=0¦Orientation=2¦PaperLength=1000¦PaperWidth=1000¦Scale=100¦PaperSource=15¦PrintQuality=600¦MediaType=1¦DitherType=10¦PaperKind=Letter¦PrintScaleMode=1

## Sheet TIDA-050072_CoverSheet.SchDoc
size 431 x 279 mm; Date: Not shown in title block; ApprovedBy: Not shown in title block; CheckedBy: Not shown in title block; Author: Not shown in title block; CompanyName: Not shown in title block; Engineer: Not shown in title block; Organization: Not shown in title block; Address1: Not shown in title block; Address2: Not shown in title block; Address3: Not shown in title block; Address4: Not shown in title block; DocumentNumber: 1; Revision: Use project parameter SCH_Rev; SheetNumber: 1; SheetTotal: 4; PageSetup: Record=PageOptions¦CenterHorizontal=True¦CenterVertical=True¦PrintScale=1.00¦XCorrection=1.00¦YCorrection=1.00¦PrintKind=0¦BorderSize=5000000¦LeftOffset=0¦BottomOffset=0¦Orientation=2¦PaperLength=1000¦PaperWidth=1000¦Scale=100¦PaperSource=15¦PrintQuality=600¦MediaType=1¦DitherType=10¦PaperKind=Letter¦PrintScaleMode=1
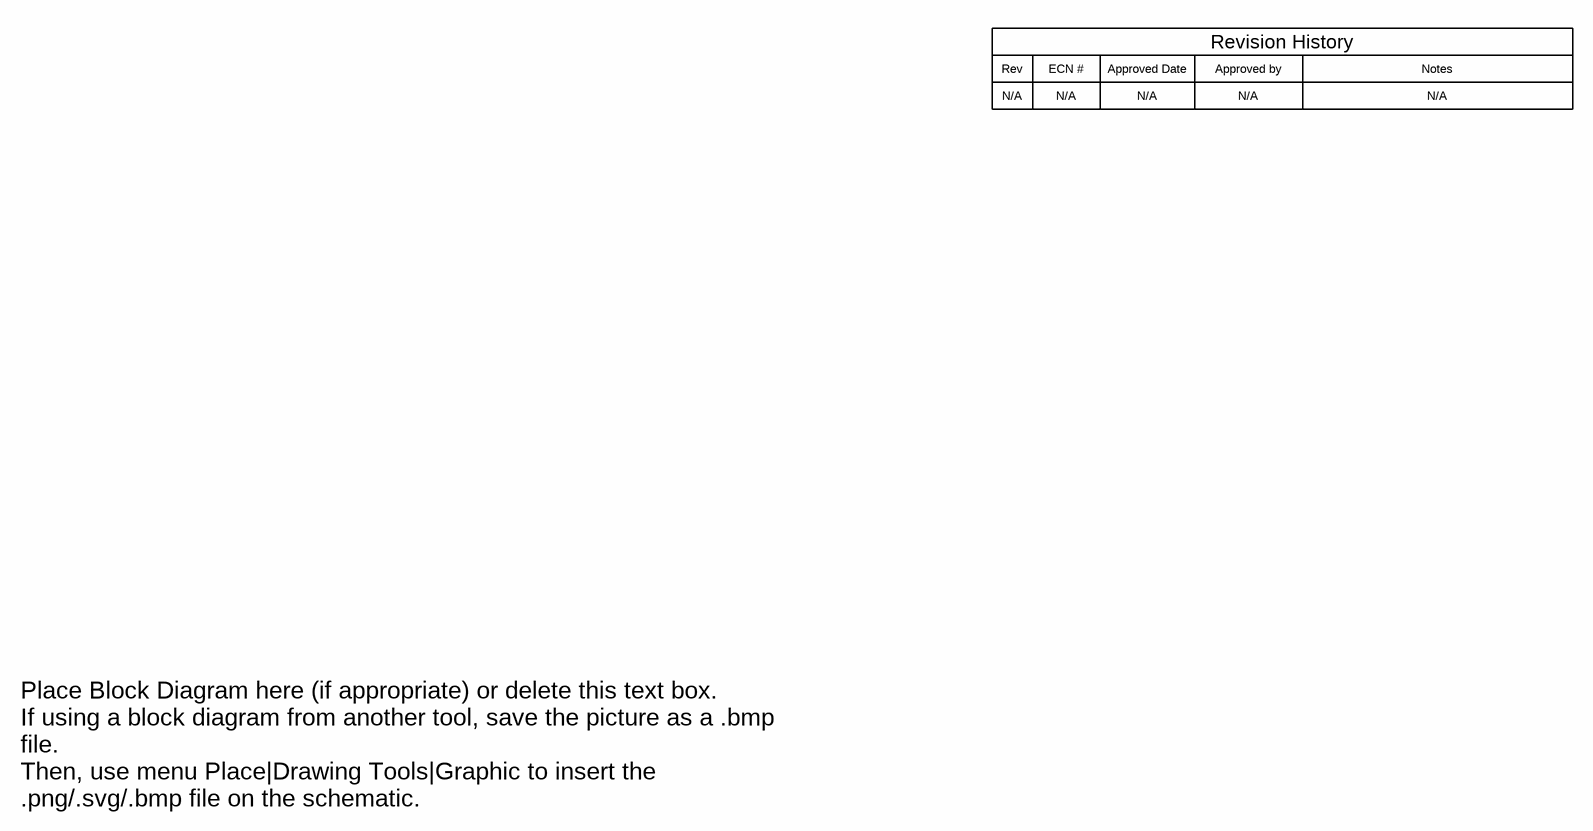
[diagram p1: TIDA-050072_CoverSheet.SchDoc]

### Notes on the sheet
- Rev
- N/A
- ECN #
- Approved Date
- Approved by
- Revision History
- Notes
- Place Block Diagram here (if appropriate) or delete this text box.
  If using a block diagram from another tool, save the picture as a .bmp file.
  Then, use menu Place|Drawing Tools|Graphic to insert the .png/.svg/.bmp file on the schematic.

## Sheet TIDA-050072_Hardware.SchDoc
size 431 x 279 mm; Date: Not shown in title block; ApprovedBy: Not shown in title block; CheckedBy: Not shown in title block; Author: Not shown in title block; CompanyName: Not shown in title block; Engineer: Not shown in title block; Organization: Not shown in title block; Address1: Not shown in title block; Address2: Not shown in title block; Address3: Not shown in title block; Address4: Not shown in title block; DocumentNumber: 4; Revision: Use project parameter SCH_Rev; SheetNumber: 4; SheetTotal: 4; PageSetup: Record=PageOptions¦CenterHorizontal=True¦CenterVertical=True¦PrintScale=1.00¦XCorrection=1.00¦YCorrection=1.00¦PrintKind=0¦BorderSize=5000000¦LeftOffset=0¦BottomOffset=0¦Orientation=2¦PaperLength=1000¦PaperWidth=1000¦Scale=100¦PaperSource=15¦PrintQuality=600¦MediaType=1¦DitherType=10¦PaperKind=Letter¦PrintScaleMode=1
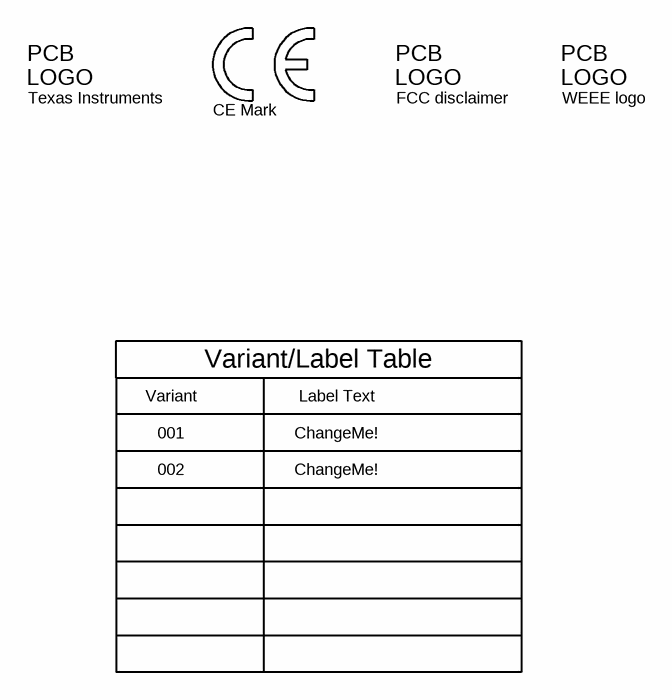
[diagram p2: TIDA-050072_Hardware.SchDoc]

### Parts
Logo1  Texas Instruments  [TI_Stacked_Overlay_Small]  (no BOM)
Logo2  CE Mark  [CE_Mark_5mm]  (no BOM)
Logo3  FCC disclaimer  [FCC_disclaimer]  (no BOM)
Logo4  WEEE logo  [WEEE_Minimum]  (no BOM)

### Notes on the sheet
- Variant
- Variant/Label Table
- Label Text
- 001
- 002
- ChangeMe!

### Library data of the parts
Logo1 = CMP-0074838-1: Texas Instrument Corporate Signature; SymbolCreator: a0412235; Lib Reference: TI_Logo; Library Reference: Logo
Logo2 = CMP-0074844-1: SymbolCreator: a0412235
Logo3 = CMP-0074847-1: FCC_disclaimer; Library Reference: Logo
Logo4 = CMP-0074769-1

## Sheet TIDA-050072_PD_Board.SchDoc
size 431 x 279 mm; Date: Not shown in title block; ApprovedBy: Not shown in title block; CheckedBy: Not shown in title block; Author: Not shown in title block; CompanyName: Not shown in title block; Engineer: Not shown in title block; Organization: Not shown in title block; Address1: Not shown in title block; Address2: Not shown in title block; Address3: Not shown in title block; Address4: Not shown in title block; DocumentNumber: 3; Revision: Use project parameter SCH_Rev; SheetNumber: 3; SheetTotal: 4; PageSetup: Record=PageOptions¦CenterHorizontal=True¦CenterVertical=True¦PrintScale=1.00¦XCorrection=1.00¦YCorrection=1.00¦PrintKind=0¦BorderSize=5000000¦LeftOffset=0¦BottomOffset=0¦Orientation=2¦PaperLength=1000¦PaperWidth=1000¦Scale=100¦PaperSource=15¦PrintQuality=600¦MediaType=1¦DitherType=10¦PaperKind=Letter¦PrintScaleMode=1
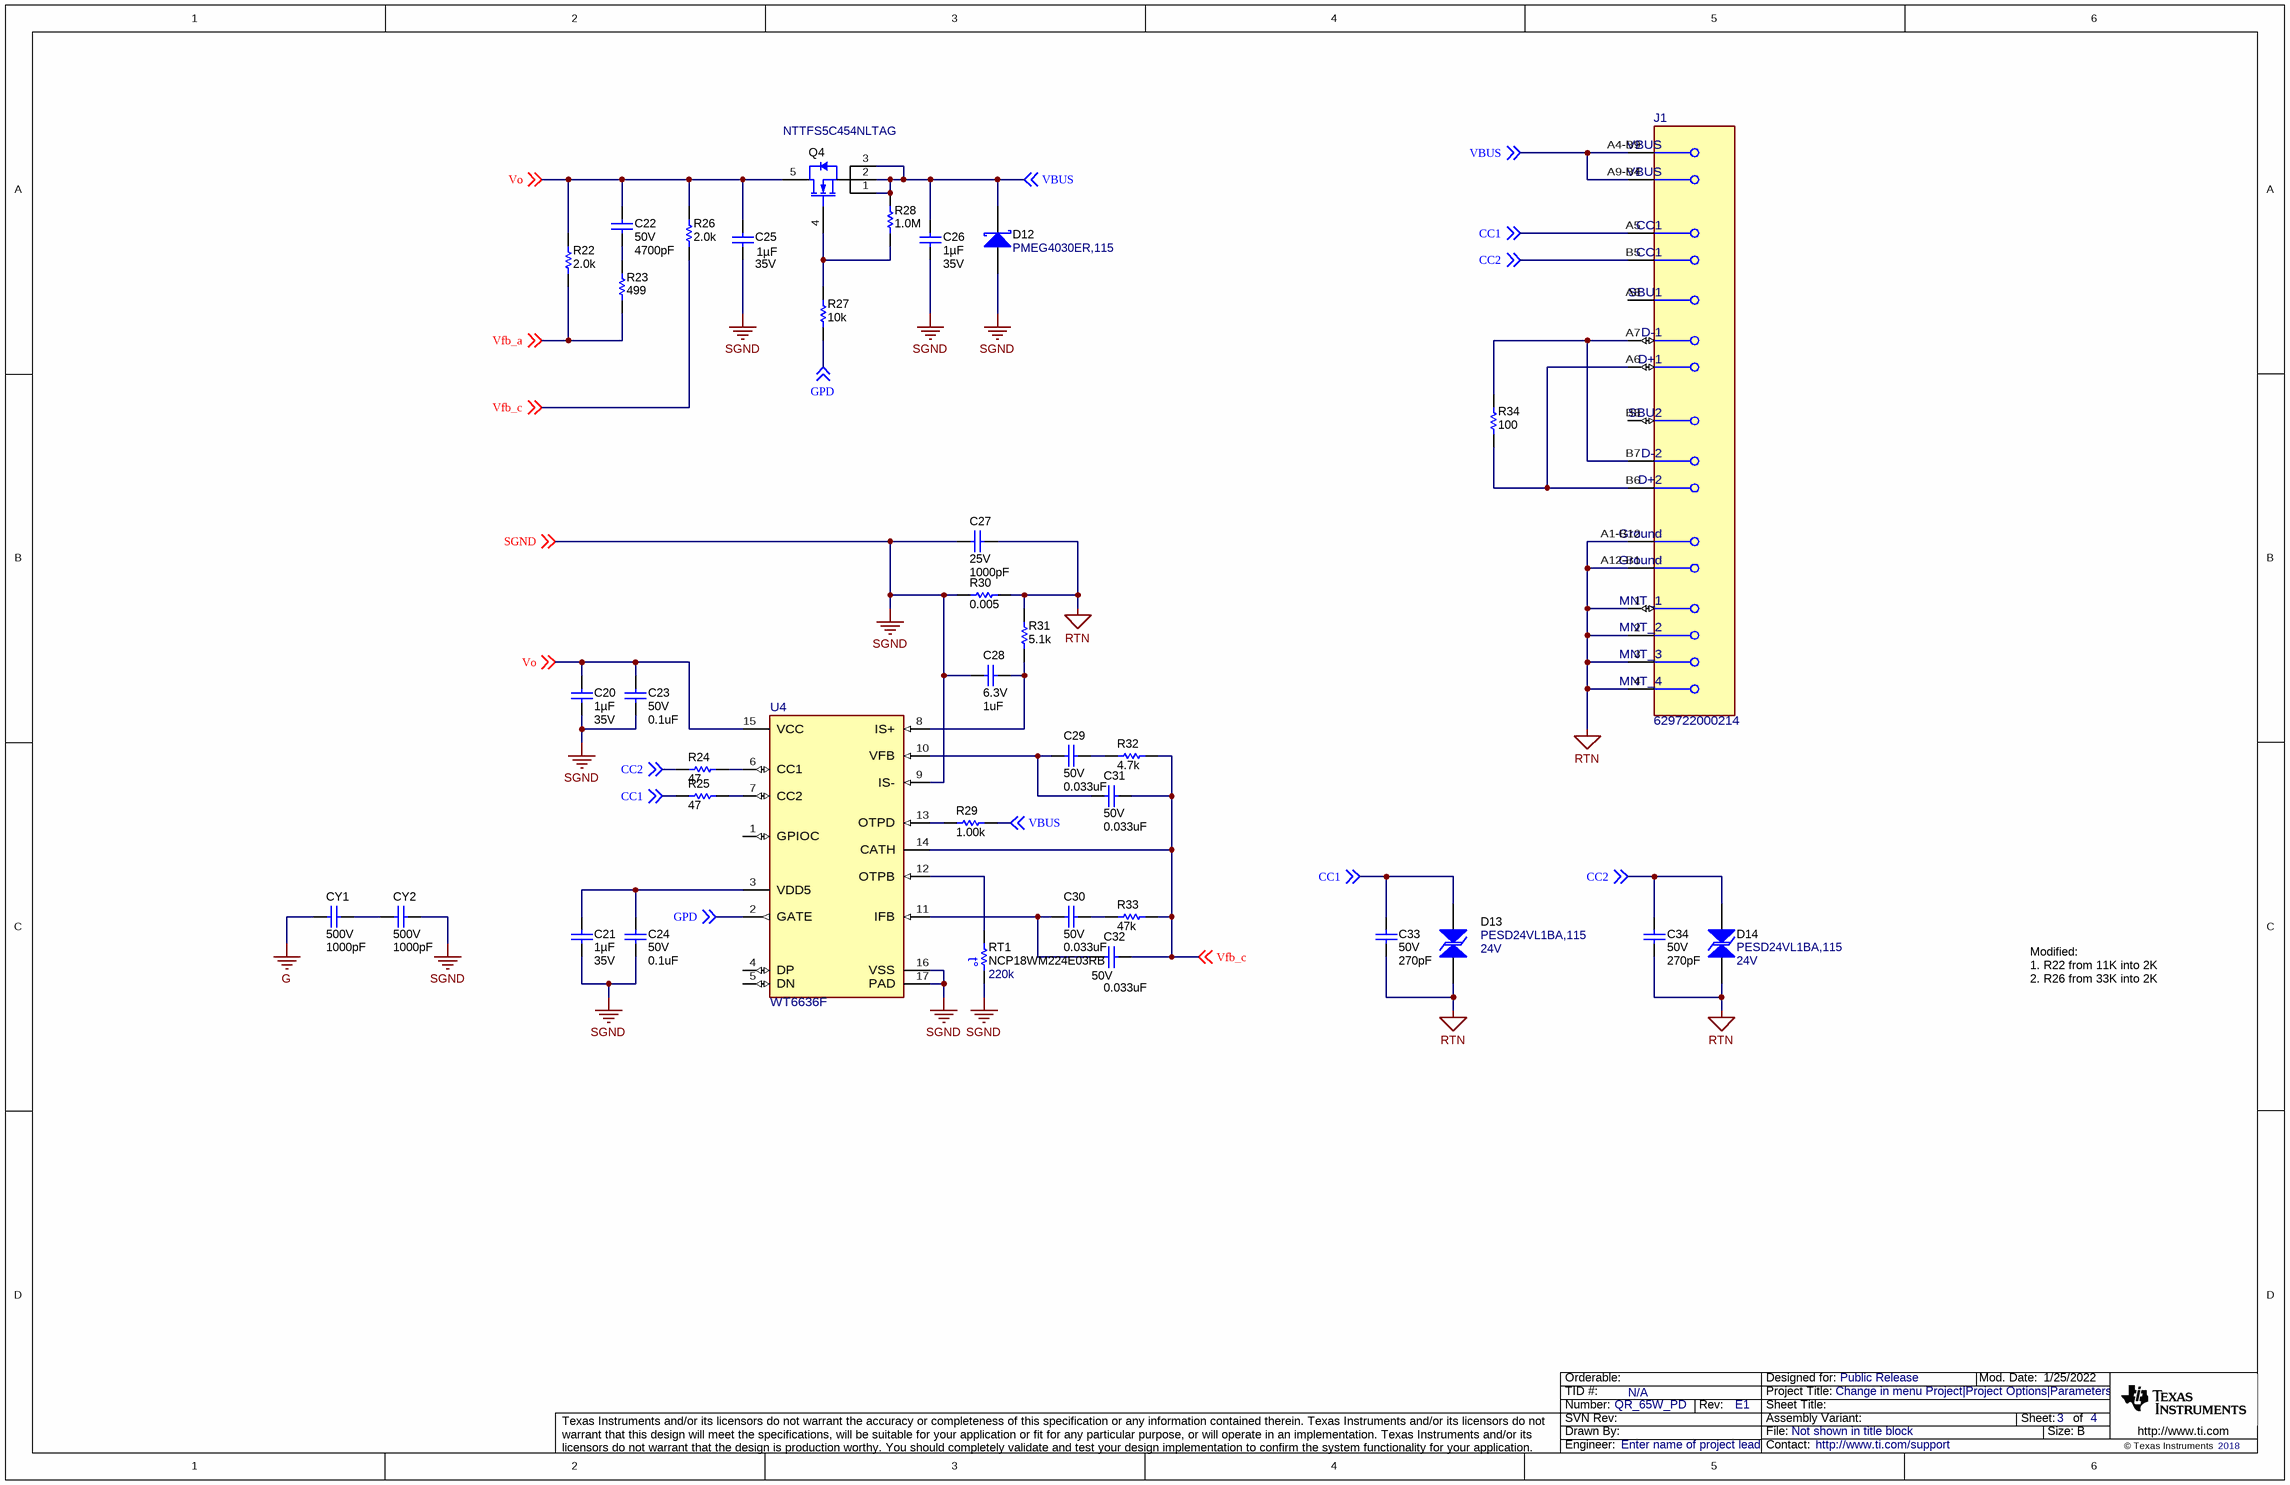
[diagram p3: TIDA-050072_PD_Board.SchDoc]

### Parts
C20  Cap_F: 1µF  VDC_V: 35V  [0603_HV]  (hidden comment: C1608X7R1V105K080AC)
C21  Cap_F: 1µF  VDC_V: 35V  [0603_HV]  (hidden comment: C1608X7R1V105K080AC)
C22  VDC_V: 50V  ValueDisplayed: 4700pF  [0402]  (hidden comment: CGA2B2X7R1H472K050BA)
C23  VDC_V: 50V  ValueDisplayed: 0.1uF  [0402]  (hidden comment: GRM155R71H104ME14D)
C24  VDC_V: 50V  ValueDisplayed: 0.1uF  [0402]  (hidden comment: GRM155R71H104ME14D)
C25  Cap_F: 1µF  VDC_V: 35V  [0603_HV]  (hidden comment: C1608X7R1V105K080AC)
C26  Cap_F: 1µF  VDC_V: 35V  [0603_HV]  (hidden comment: C1608X7R1V105K080AC)
C27  VDC_V: 25V  ValueDisplayed: 1000pF  [0603_HV]  (hidden comment: C0603C102K3GACTU)
C28  VDC_V: 6.3V  ValueDisplayed: 1uF  [0402]  (hidden comment: GRM155R70J105KA12D)
C29  VDC_V: 50V  ValueDisplayed: 0.033uF  [0402]  (hidden comment: CGA2B3X7R1H333K050BB)
C30  VDC_V: 50V  ValueDisplayed: 0.033uF  [0402]  (hidden comment: CGA2B3X7R1H333K050BB)
C31  VDC_V: 50V  ValueDisplayed: 0.033uF  [0402]  (hidden comment: CGA2B3X7R1H333K050BB)
C32  VDC_V: 50V  ValueDisplayed: 0.033uF  [0402]  (hidden comment: CGA2B3X7R1H333K050BB)
C33  VDC_V: 50V  ValueDisplayed: 270pF  [0402]  (hidden comment: GRM1555C1H271JA01D)
C34  VDC_V: 50V  ValueDisplayed: 270pF  [0402]  (hidden comment: GRM1555C1H271JA01D)
CY1  VDC_V: 500V  ValueDisplayed: 1000pF  [1808_L]  (hidden comment: VJ1808Y102KXEAT5Z)
CY2  VDC_V: 500V  ValueDisplayed: 1000pF  [1808_L]  (hidden comment: VJ1808Y102KXEAT5Z)
D12  PMEG4030ER,115  [SOD-123W]
D13  PESD24VL1BA,115  value 24V  [SOD-323-Bi]
D14  PESD24VL1BA,115  value 24V  [SOD-323-Bi]
J1  629722000214  [FP-629722000214_CONN_USB-MFG]
Q4  NTTFS5C454NLTAG  [Power_WDFN-8]
R22  ValueDisplayed: 2.0k  [0402]  (hidden comment: CRCW04022K00JNED)
R23  ValueDisplayed: 499  [0402]  (hidden comment: CRCW0402499RFKED)
R24  ValueDisplayed: 47  [0402]  (hidden comment: MCR01MZPJ470)
R25  ValueDisplayed: 47  [0402]  (hidden comment: MCR01MZPJ470)
R26  ValueDisplayed: 2.0k  [0402]  (hidden comment: CRCW04022K00JNED)
R27  ValueDisplayed: 10k  [0603_HV]  (hidden comment: RC0603JR-0710KL)
R28  ValueDisplayed: 1.0M  [0402]  (hidden comment: CRCW04021M00JNED)
R29  ValueDisplayed: 1.00k  [0603_HV]  (hidden comment: CRCW06031K00FKEA)
R30  ValueDisplayed: 0.005  [1206]  (hidden comment: CSR1206-0R005F1)
R31  ValueDisplayed: 5.1k  [0402]  (hidden comment: CRCW04025K10JNED)
R32  ValueDisplayed: 4.7k  [0402]  (hidden comment: CRCW04024K70JNED)
R33  ValueDisplayed: 47k  [0402]  (hidden comment: CRCW040247K0JNED)
R34  ValueDisplayed: 100  [0603_HV]  (hidden comment: CRCW0603100RJNEA)
RT1  NCP18WM224E03RB  value 220k  [0603_HV]
U4  WT6636F  [FP-WT6636F_QFN16-IPC_B]

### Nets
G: CY1.2
RTN: C27.1 C33.2 C34.2 D13.1 D14.1 J1.1(MNT_1) J1.2(MNT_2) J1.3(MNT_3) J1.4(MNT_4) J1.A1-B12(Ground) J1.A12-B1(Ground) R30.2 R31.2
SGND: C20.2 C21.2 C23.2 C24.2 C25.2 C26.2 C27.2 C28.1 CY2.1 D12.2(A) R30.1 RT1.2 U4.9(IS-) U4.16(VSS) U4.17(PAD) ; off-sheet SGND
CC1: C33.1 D13.2 J1.A5(CC1) R25.1 ; off-sheet CC1
CC2: C34.1 D14.2 J1.B5(CC1) R24.1 ; off-sheet CC2
GPD: R27.1 U4.2(GATE) ; off-sheet GPD
VBUS: C26.1 D12.1(K) J1.A4-B9(VBUS) J1.A9-B4(VBUS) Q4.1(S) Q4.2(S) Q4.3(S) R28.2 R29.2 ; off-sheet VBUS
Vfb_a: R22.1 R23.1 ; off-sheet Vfb_a
Vfb_c: C31.1 C32.1 R26.1 R32.2 R33.2 U4.14(CATH) ; off-sheet Vfb_c
Vo: C20.1 C22.1 C23.1 C25.1 Q4.5(D) R22.2 R26.2 U4.15(VCC) ; off-sheet Vo
NetC21_1: C21.1 C24.1 U4.3(VDD5)
NetC22_2: C22.2 R23.2
NetC28_2: C28.2 R31.1 U4.8(IS+)
NetC29_1: C29.1 R32.1
NetC29_2: C29.2 C31.2 U4.10(VFB)
NetC30_1: C30.1 R33.1
NetC30_2: C30.2 C32.2 U4.11(IFB)
NetCY1_1: CY1.1 CY2.2
NetJ1_A6: J1.A6(D+1) J1.B6(D+2) R34.1
NetJ1_A7: J1.A7(D-1) J1.B7(D-2) R34.2
NetQ4_4: Q4.4(G) R27.2 R28.1
NetR24_2: R24.2 U4.6(CC1)
NetR25_2: R25.2 U4.7(CC2)
NetR29_1: R29.1 U4.13(OTPD)
NetRT1_1: RT1.1 U4.12(OTPB)

Not connected (* = marked no-connect by the designer): J1 A8(SBU1) B8(SBU2); U4 1(GPIOC) 4(DP) 5(DN)

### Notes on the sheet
- Modified:
  1. R22 from 11K into 2K
  2. R26 from 33K into 2K

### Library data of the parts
C20 C21 C25 C26 = CMP-0007052-2: CAP, CERM, 1 uF, 35 V, +/- 10%, X7R, 0603; Manufacturer: TDK; TaMin_C: -55°C; Polarized: N; SizeAreaWB_mm2: 4.68; Value1: Unknown; U/M: EA; Value: 1uF; TaMax_C: 125°C; SizeZ_mm: 1; SizeX_mm: 1.6; SizeY_mm: 0.8; Cap_Case: 0603; SizeArea_mm2: 1.28; AEC Category: Q200
C22 = CMP-0006321-1: CAP, CERM, 4700 pF, 50 V, +/- 10%, X7R, AEC-Q200 Grade 1, 0402; Manufacturer: TDK; TaMin_C: -55°C; ESR_ohm: 0.413508; Polarized: N; SizeAreaWB_mm2: 3; Value1: 0.413508 ohm; U/M: EA; Value: 4700pF; TaMax_C: 125°C; SizeZ_mm: 0.6; SizeX_mm: 1; SizeY_mm: 0.5; AEC Qualified: Y; Cap_F: 4.7nF; IRMS_A: 330.878mA; AEC Category: Q200
C23 C24 = CMP-0006675-1: CAP, CERM, 0.1 uF, 50 V, +/- 20%, X7R, 0402; Manufacturer: MuRata; TaMin_C: -55°C; Polarized: N; SizeAreaWB_mm2: 3; Value1: Unknown; U/M: EA; Value: 0.1uF; TaMax_C: 125°C; SizeZ_mm: 0.6; SizeX_mm: 1; SizeY_mm: 0.5; Cap_F: 100nF; AEC Category: Q200
C27 = CMP-0006846-1: CAP, CERM, 1000 pF, 25 V, +/- 10%, C0G/NP0, 0603; Manufacturer: Kemet; TaMin_C: -55°C; ESR_ohm: 0; Polarized: N; SizeAreaWB_mm2: 4.68; Value1: 0 ohm; U/M: EA; Value: 1000pF; TaMax_C: 125°C; SizeZ_mm: 1; SizeX_mm: 1.6; SizeY_mm: 0.8; Cap_Case: 0603; SizeArea_mm2: 1.28; Cap_F: 1nF; IRMS_A: 0A; AEC Category: Q200
C28 = CMP-0064947-2: CAP, CERM, 1 uF, 6.3 V,+/- 10%, X7R, 0402; Manufacturer: MuRata; TaMin_C: -55°C; Polarized: N; SizeAreaWB_mm2: 3; Value1: Unknown; U/M: EA; Value: 1uF; TaMax_C: 125°C; SizeZ_mm: 0.6; SizeX_mm: 1; SizeY_mm: 0.5; Cap_F: 1µF; AEC Category: Q200
C29-C32 = CMP-0006329-1: CAP, CERM, 0.033 uF, 50 V, +/- 10%, X7R, AEC-Q200 Grade 1, 0402; Manufacturer: TDK; TaMin_C: -55°C; ESR_ohm: 0.098477; Polarized: N; SizeAreaWB_mm2: 3; Value1: 0.098477 ohm; U/M: EA; TaMax_C: 125°C; SizeZ_mm: 0.6; SizeX_mm: 1; SizeY_mm: 0.5; AEC Qualified: Y; Cap_F: 33nF; IRMS_A: 530.78mA; AEC Category: Q200
C33 C34 = CMP-0006445-1: CAP, CERM, 270 pF, 50 V, +/- 5%, C0G/NP0, 0402; Manufacturer: MuRata; TaMin_C: -55°C; Polarized: N; SizeAreaWB_mm2: 3; Value1: Unknown; U/M: EA; Value: 270pF; TaMax_C: 125°C; SizeZ_mm: 0.6; SizeX_mm: 1; SizeY_mm: 0.5; AEC Category: Q200
CY1 CY2 = CMP-0009539-1: CAP, CERM, 1000 pF, 500 V, +/- 10%, X7R, 1808; Manufacturer: Vishay-Vitramon; TaMin_C: -55°C; Polarized: N; SizeAreaWB_mm2: 16.5; Value1: Unknown; U/M: EA; Value: 1000pF; TaMax_C: 125°C; SizeZ_mm: 2.03; SizeX_mm: 4.5; SizeY_mm: 2; Cap_Case: 1808; SizeArea_mm2: 9; Cap_F: 1nF; AEC Category: Q200
D12 = CMP-0080763-2: Diode, Schottky, 40 V, 3 A, AEC-Q101, SOD-123W; Manufacturer: Nexperia; Value2: 0.54V; AEC Category: Q101; SizeArea_mm2: 5.95; AEC Qualified: Y; Io_A: 3A; SizeZ_mm: 1; Value: 40V; SizeY_mm: 1.7; Vf_V: 540mV; SizeAreaWB_mm2: 12.15; SizeX_mm: 3.5; TJmax_C: 150°C
D13 D14 = CMP-0006061-5: Diode, TVS, Bi, 24 V, 70 Vc, SOD323; Manufacturer: NXP Semiconductor; Vc: 70V; Vbr_Min: 25.4V; AEC Category: Q101; Ppk: 200W; Ipp: 3A; AEC Qualified: N; Vbr_Max: 30.3V
J1 = CMP-0095999-1: Conenctor USB 2.0 Type C Horizontal SMT; Manufacturer: GCT; PartNumber: USB4105-GF-A; Current_A: 5A; ContactFinish: Gold,Nickel; AEC Qualified: No; Shrouded: true; Voltage_V: 20V; SizeZ_mm: 3.51mm; Usb Standard: USB 2.0; Is Female: yes
Q4 = CMP-0000732-1: MOSFET, N-CH, 40 V, 20 A, 8-PowerWDFN; Alternate Manufacturer: None; Manufacturer: ON Semiconductor; SizeZ_mm: 0.8; ChType: N; Value2: 18 nC; Value1: 0; VdsMax_V: 40V; SizeX_mm: 3.3; Vgs_V: 20V; Value: 40V; Rdson45_ohm: 6m; SizeArea_mm2: 10.89; AEC Category: Q101; IdsMax_A: 20A; SizeAreaWB_mm2: 18.49; U/M: EA; QgTyp_nC: 18
R22 R26 = CMP-0026889-2: RES, 2.0 k, 5%, 0.063 W, 0402; Manufacturer: Vishay-Dale; Power_W: 63mW; TempCo: 200 ppm/C; Value_Code: 2k00; U/M: EA; Value: 2.0k; EIA_Code: E24; Res_ohm: 2k; SizeX_mm: 1; SizeY_mm: 0.5; SizeZ_mm: 0.6; Value2: 0.063W; VDC_V: 50V; AEC Category: Q200
R23 = CMP-0026402-1: RES, 499, 1%, 0.063 W, 0402; Manufacturer: Vishay-Dale; Power_W: 63mW; TempCo: 100 ppm/C; Value_Code: 499R; U/M: EA; Value: 499; EIA_Code: E96; SizeX_mm: 1; SizeY_mm: 0.5; SizeZ_mm: 0.6; Value2: 0.063W; VDC_V: 50V; AEC Category: Q200
R24 R25 = CMP-0027003-2: RES, 47, 5%, 0.063 W, 0402; Manufacturer: Rohm; Power_W: 63mW; TempCo: 200 ppm/C; Value_Code: 47R0; U/M: EA; Value: 47; EIA_Code: E24; SizeX_mm: 1; SizeY_mm: 0.5; SizeZ_mm: 0.6; Value2: 0.063W; AEC Qualified: N; AEC Category: Q200
R27 = CMP-0025886-5: RES, 10 k, 5%, 0.1 W, 0603; Manufacturer: Yageo; Power_W: 100mW; TempCo: 100 ppm/C; Value_Code: 10k0; Value: 10k; EIA_Code: E24; SizeX_mm: 1.6; SizeY_mm: 0.8; SizeZ_mm: 1; Value2: 0.1W; SizeArea_mm2: 1.28; AEC Qualified: N; VDC_V: 75V; AEC Category: Q200; SizeAreaWB_mm2: 4.68
R28 = CMP-0026859-2: RES, 1.0 M, 5%, 0.063 W, AEC-Q200 Grade 0, 0402; Manufacturer: Vishay-Dale; Power_W: 63mW; TempCo: 200 ppm/C; Value_Code: 1M00; Value: 1.0Meg; EIA_Code: E24; Res_ohm: 1M; SizeX_mm: 1; SizeY_mm: 0.5; SizeZ_mm: 0.6; Value2: 0.063W; AEC Qualified: Y; VDC_V: 50V; AEC Category: Q200; AEC Grade: 0
R29 = CMP-0022109-1: RES, 1.00 k, 1%, 0.1 W, 0603; Manufacturer: Vishay-Dale; Power_W: 100mW; TempCo: 100 ppm/C; Value_Code: 1k00; U/M: EA; Value: 1.00k; EIA_Code: E96; Res_ohm: 1k; SizeX_mm: 1.6; SizeY_mm: 0.8; SizeZ_mm: 1; Value2: 0.1W; SizeArea_mm2: 1.28; VDC_V: 75V; AEC Category: Q200
R30 = CMP-0078497-1: RES, 0.005, 1%, 1 W, 1206; Manufacturer: Riedon; Power_W: 1W; TempCo: 50 ppm/C; Value_Code: 5L000; Value: 0.005; EIA_Code: E96; Res_ohm: 5m; SizeX_mm: 3.2; SizeY_mm: 1.6; SizeZ_mm: 1.35; SizeArea_mm2: 5.12; AEC Qualified: N; AEC Category: Q200
R31 = CMP-0026951-3: RES, 5.1 k, 5%, 0.063 W, 0402; Manufacturer: Vishay-Dale; Power_W: 63mW; TempCo: 200 ppm/C; Value_Code: 5k10; U/M: EA; Value: 5.1k; EIA_Code: E24; SizeX_mm: 1; SizeY_mm: 0.5; SizeZ_mm: 0.6; Value2: 0.063W; VDC_V: 50V; AEC Category: Q200
R32 = CMP-0026938-5: RES, 4.7 k, 5%, 0.063 W, AEC-Q200 Grade 0, 0402; Manufacturer: Vishay-Dale; Power_W: 63mW; TempCo: 200 ppm/C; Value_Code: 4k70; Value: 4.7k; EIA_Code: E24; SizeX_mm: 1; SizeY_mm: 0.5; SizeZ_mm: 0.6; Value2: 0.063W; AEC Qualified: Y; VDC_V: 50V; AEC Category: Q200; AEC Grade: 0
R33 = CMP-0026935-2: RES, 47 k, 5%, 0.063 W, 0402; Manufacturer: Vishay-Dale; Power_W: 63mW; TempCo: 200 ppm/C; Value_Code: 47k0; U/M: EA; Value: 47k; EIA_Code: E24; SizeX_mm: 1; SizeY_mm: 0.5; SizeZ_mm: 0.6; Value2: 0.063W; VDC_V: 50V; AEC Category: Q200
R34 = CMP-0025700-3: RES, 100, 5%, 0.1 W, 0603; Manufacturer: Vishay-Dale; Power_W: 100mW; TempCo: 200 ppm/C; Value_Code: 100R; U/M: EA; Value: 100; EIA_Code: E24; SizeX_mm: 1.6; SizeY_mm: 0.8; SizeZ_mm: 1; Value2: 0.1W; SizeArea_mm2: 1.28; VDC_V: 75V; AEC Category: Q200
RT1 = CMP-0002440-2: Thermistor NTC, 220k ohm, 3%, 0603; Manufacturer: MuRata; TaMax_C: 125°C; SizeX_mm: 1.6; SizeY_mm: 0.8; TaMin_C: -40°C; Power_W: 100mW; SizeZ_mm: 1; SizeArea_mm2: 1.28; SizeAreaWB_mm2: 4.68; U/M: EA
U4 = CMP-0087009-1: USB PD/QC4/QC4+ Controller; Manufacturer: Weltrend; SizeZ_mm: 0.8mm

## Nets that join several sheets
G: TIDA-050072 (38 pins), TIDA-050072_PD_Board (CY1.2)
SGND: TIDA-050072 (-.1 C18.2 C19.2 D11.2), TIDA-050072_PD_Board (15 pins)
Vfb_a: TIDA-050072 (Q2.1), TIDA-050072_PD_Board (R22.1 R23.1)
Vfb_c: TIDA-050072 (Q2.3), TIDA-050072_PD_Board (6 pins)
Vo: TIDA-050072 (9 pins), TIDA-050072_PD_Board (8 pins)

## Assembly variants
001: not fitted + - CM1 L1 N1 R4 T1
